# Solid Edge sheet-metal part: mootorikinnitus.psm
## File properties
Author: Argo
Template: Normal.psm
Last saved by: haldur
Revision: 15
Application: Solid Edge
Material: Aluminum, 3004
Face Style: Aluminum
Fill Style: ANSI38(Aluminum)
Virtual Style: Polished aluminum
Coef. of Thermal Exp: 2.3e-05
Thermal Conductivity: 170.0
Specific Heat: 920.0
Modulus of Elasticity: 68947570000.0
Poission's Ratio: 0.33
Yield Stress: 68947570.0
Ultimate Stress: 179263682.0
Elongation: 0.0
Density: 2712,000 kg/m^3
Accuracy: 0,990
Material Thickness: 0,50 mm
Bend Radius: 1,00 mm
Relief Width: 1,00 mm
Relief Length: 0,00 mm
Neutral Factor: 0,330
Minimum Arc Length: 0,10 mm
Deviational Tolerance: 0,10 mm
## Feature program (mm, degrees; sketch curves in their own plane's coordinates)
base tab "unnamed BaseTab 1"
flange "Flange_2"
flange "Flange_3"
sheet metal cutout "unnamed SheetMetalCutout 1"
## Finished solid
Body 1: solid body, 22 faces, 52 edges, 24 vertices.
  Faces by surface: cylinder 12, plane 10
  Edges by curve: line 28, circle 24
Bounding box of the edges (mm): 50.000 x 7.000 x 18.930, from (-25, 0, -8.715) to (25, 7, 10.215).
Cylindrical faces by radius (mm): R1 x10, R1.5 x2
Planar faces by outward normal: +x 1, +y 2, +z 1, -x 1, -y 2, -z 3
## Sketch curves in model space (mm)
circle centre (8, 0, 0) radius 1
circle centre (16, 0, 0) radius 1
circle centre (-8, 0, 0) radius 1
circle centre (-16, 0, 0) radius 1
line (25, 0, -8.715) -> (25, 0, 8.715)
line (25, 0, 8.715) -> (-25, 0, 8.715)
line (-25, 0, 8.715) -> (-25, 0, -8.715)
line (-25, 0, -8.715) -> (25, 0, -8.715)
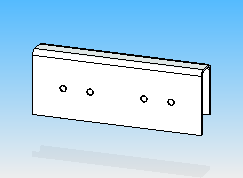
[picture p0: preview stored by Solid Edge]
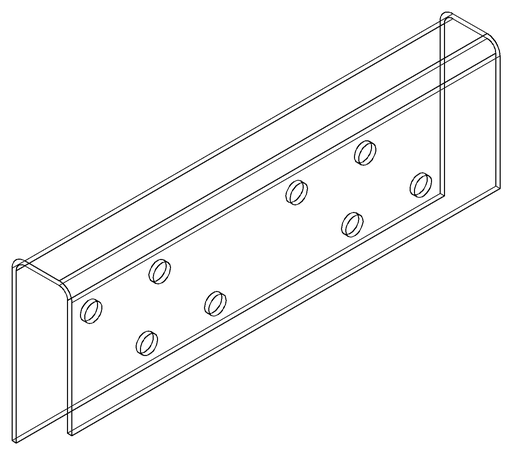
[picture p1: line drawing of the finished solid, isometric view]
